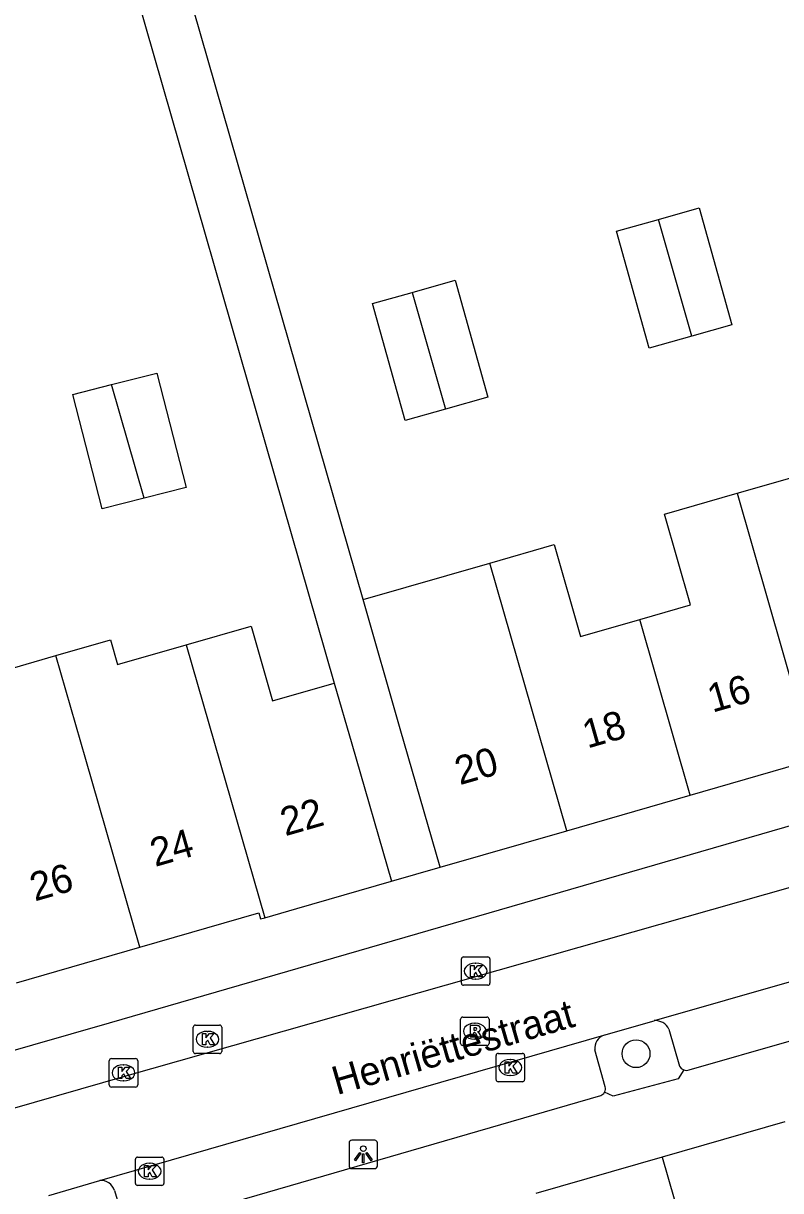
# Model space of a CAD drawing. Extents: x 159718 to 160783, y 383290 to 384030.
# Drawn here: x 160324.72 to 160351.34, y 383596.25 to 383637.31 of the extents above; entities that cross this region are included whole.
import ezdxf

# ---------------------------------------------------------------- set-up
doc = ezdxf.new("R2010")
doc.units = 0
for name, color, linetype in [('IMGEO_Boom', 7, 'Continuous'), ('IMGEO_Kolk', 7, 'Continuous'), ('IMGEO_Lichtpunt', 7, 'Continuous'), ('IMGEO_Openbare_ruimte_label', 7, 'Continuous'), ('IMGEO_Pand', 7, 'Continuous'), ('IMGEO_Pand_nummerreeks', 7, 'Continuous'), ('IMGEO_Parkeervlak_open', 7, 'Continuous'), ('IMGEO_Rijbaan_lokaal_open', 7, 'Continuous'), ('IMGEO_Rioolput', 7, 'Continuous'), ('IMGEO_Voetpad_open', 7, 'Continuous')]:
    doc.layers.add(name, color=color, linetype=linetype)

msp = doc.modelspace()

# ---------------------------------------------------------------- linework, layer by layer
at = {"layer": 'IMGEO_Boom'}
msp.add_circle((160346.26, 383601.066), 0.489, dxfattribs=at)
at = {"layer": 'IMGEO_Kolk'}
for p, q in [((160340.118, 383603.547), (160340.118, 383604.399)), ((160340.193, 383604.473), (160341.045, 383604.473)), ((160341.119, 383604.399), (160341.119, 383603.547)), ((160340.606, 383604.253), (160340.631, 383604.253)), ((160340.629, 383603.693), (160340.604, 383603.693)), ((160341.045, 383603.473), (160340.193, 383603.473)), ((160330.69, 383601.148), (160330.69, 383602)), ((160330.765, 383602.074), (160331.617, 383602.074)), ((160331.178, 383601.854), (160331.203, 383601.854)), ((160331.691, 383602), (160331.691, 383601.148)), ((160331.617, 383601.074), (160330.765, 383601.074)), ((160331.201, 383601.294), (160331.176, 383601.294)), ((160341.414, 383601.08), (160342.266, 383601.08)), ((160327.737, 383599.967), (160327.737, 383600.819)), ((160327.812, 383600.893), (160328.664, 383600.893)), ((160328.225, 383600.673), (160328.25, 383600.673)), ((160328.738, 383600.819), (160328.738, 383599.967)), ((160341.339, 383600.154), (160341.339, 383601.006)), ((160341.827, 383600.86), (160341.852, 383600.86)), ((160342.34, 383601.006), (160342.34, 383600.154)), ((160341.85, 383600.3), (160341.825, 383600.3)), ((160328.664, 383599.893), (160327.812, 383599.893)), ((160328.248, 383600.113), (160328.223, 383600.113)), ((160342.266, 383600.08), (160341.414, 383600.08)), ((160328.659, 383596.506), (160328.659, 383597.358)), ((160328.734, 383597.432), (160329.586, 383597.432)), ((160329.66, 383597.358), (160329.66, 383596.506)), ((160329.147, 383597.212), (160329.172, 383597.212)), ((160329.17, 383596.652), (160329.145, 383596.652)), ((160329.586, 383596.432), (160328.734, 383596.432))]:
    msp.add_line(p, q, dxfattribs=at)
for points in [[(160340.118, 383603.547), (160340.118, 383604.399)], [(160340.193, 383604.473), (160341.045, 383604.473)], [(160341.119, 383604.399), (160341.119, 383603.547)], [(160340.439, 383604.173), (160340.562, 383604.173), (160340.562, 383604.022), (160340.692, 383604.173), (160340.856, 383604.173), (160340.71, 383604.022), (160340.863, 383603.773), (160340.711, 383603.773), (160340.626, 383603.937), (160340.562, 383603.87), (160340.562, 383603.773), (160340.439, 383603.773), (160340.439, 383604.173)], [(160341.045, 383603.473), (160340.193, 383603.473)], [(160330.69, 383601.148), (160330.69, 383602)], [(160330.765, 383602.074), (160331.617, 383602.074)], [(160331.691, 383602), (160331.691, 383601.148)], [(160331.011, 383601.774), (160331.134, 383601.774), (160331.134, 383601.623), (160331.264, 383601.774), (160331.428, 383601.774), (160331.282, 383601.623), (160331.435, 383601.374), (160331.283, 383601.374), (160331.198, 383601.538), (160331.134, 383601.471), (160331.134, 383601.374), (160331.011, 383601.374), (160331.011, 383601.774)], [(160331.617, 383601.074), (160330.765, 383601.074)], [(160341.414, 383601.08), (160342.266, 383601.08)], [(160327.737, 383599.967), (160327.737, 383600.819)], [(160327.812, 383600.893), (160328.664, 383600.893)], [(160328.738, 383600.819), (160328.738, 383599.967)], [(160341.339, 383600.154), (160341.339, 383601.006)], [(160341.66, 383600.78), (160341.783, 383600.78), (160341.783, 383600.629), (160341.913, 383600.78), (160342.077, 383600.78), (160341.931, 383600.629), (160342.084, 383600.38), (160341.932, 383600.38), (160341.847, 383600.544), (160341.783, 383600.477), (160341.783, 383600.38), (160341.66, 383600.38), (160341.66, 383600.78)], [(160342.34, 383601.006), (160342.34, 383600.154)], [(160328.058, 383600.593), (160328.181, 383600.593), (160328.181, 383600.442), (160328.311, 383600.593), (160328.475, 383600.593), (160328.329, 383600.442), (160328.482, 383600.193), (160328.33, 383600.193), (160328.245, 383600.357), (160328.181, 383600.29), (160328.181, 383600.193), (160328.058, 383600.193), (160328.058, 383600.593)], [(160328.664, 383599.893), (160327.812, 383599.893)], [(160342.266, 383600.08), (160341.414, 383600.08)], [(160328.659, 383596.506), (160328.659, 383597.358)], [(160328.734, 383597.432), (160329.586, 383597.432)], [(160329.66, 383597.358), (160329.66, 383596.506)], [(160328.98, 383597.132), (160329.103, 383597.132), (160329.103, 383596.981), (160329.233, 383597.132), (160329.397, 383597.132), (160329.251, 383596.981), (160329.404, 383596.732), (160329.252, 383596.732), (160329.167, 383596.896), (160329.103, 383596.829), (160329.103, 383596.732), (160328.98, 383596.732), (160328.98, 383597.132)], [(160329.586, 383596.432), (160328.734, 383596.432)]]:
    msp.add_lwpolyline(points, dxfattribs=at)
for centre, start, end in [((160340.195, 383604.397), 91.552, 178.448), ((160340.195, 383604.397), 91.552, 178.448), ((160341.043, 383604.397), 1.552, 88.448), ((160341.043, 383604.397), 1.552, 88.448), ((160340.195, 383603.549), 181.552, 268.448), ((160340.195, 383603.549), 181.552, 268.448), ((160341.043, 383603.549), 271.552, 358.448), ((160341.043, 383603.549), 271.552, 358.448), ((160330.767, 383601.998), 91.552, 178.448), ((160330.767, 383601.998), 91.552, 178.448), ((160331.615, 383601.998), 1.552, 88.448), ((160331.615, 383601.998), 1.552, 88.448), ((160330.767, 383601.15), 181.552, 268.448), ((160330.767, 383601.15), 181.552, 268.448), ((160331.615, 383601.15), 271.552, 358.448), ((160331.615, 383601.15), 271.552, 358.448), ((160341.416, 383601.004), 91.552, 178.448), ((160341.416, 383601.004), 91.552, 178.448), ((160342.264, 383601.004), 1.552, 88.448), ((160342.264, 383601.004), 1.552, 88.448), ((160327.814, 383600.817), 91.552, 178.448), ((160327.814, 383600.817), 91.552, 178.448), ((160328.662, 383600.817), 1.552, 88.448), ((160328.662, 383600.817), 1.552, 88.448), ((160327.814, 383599.969), 181.552, 268.448), ((160327.814, 383599.969), 181.552, 268.448), ((160328.662, 383599.969), 271.552, 358.448), ((160328.662, 383599.969), 271.552, 358.448), ((160341.416, 383600.156), 181.552, 268.448), ((160341.416, 383600.156), 181.552, 268.448), ((160342.264, 383600.156), 271.552, 358.448), ((160342.264, 383600.156), 271.552, 358.448), ((160328.736, 383597.356), 91.552, 178.448), ((160328.736, 383597.356), 91.552, 178.448), ((160329.584, 383597.356), 1.552, 88.448), ((160329.584, 383597.356), 1.552, 88.448), ((160328.736, 383596.508), 181.552, 268.448), ((160328.736, 383596.508), 181.552, 268.448), ((160329.584, 383596.508), 271.552, 358.448), ((160329.584, 383596.508), 271.552, 358.448)]:
    msp.add_arc(centre, 0.0765, start, end, dxfattribs=at)
for centre, major_axis, ratio, start_param, end_param in [((160340.605, 383603.973), (-0.387, 0.002), 0.722429, 4.712389, 7.853982), ((160340.63, 383603.973), (-0.39, 0.002), 0.717154, 1.570796, 4.712389), ((160331.177, 383601.574), (-0.387, 0.002), 0.722429, 4.712389, 7.853982), ((160331.202, 383601.574), (-0.39, 0.002), 0.717154, 1.570796, 4.712389), ((160328.224, 383600.393), (-0.387, 0.002), 0.722429, 4.712389, 7.853982), ((160328.249, 383600.393), (-0.39, 0.002), 0.717154, 1.570796, 4.712389), ((160341.826, 383600.58), (-0.387, 0.002), 0.722429, 4.712389, 7.853982), ((160341.851, 383600.58), (-0.39, 0.002), 0.717154, 1.570796, 4.712389), ((160329.146, 383596.932), (-0.387, 0.002), 0.722429, 4.712389, 7.853982), ((160329.171, 383596.932), (-0.39, 0.002), 0.717154, 1.570796, 4.712389)]:
    msp.add_ellipse(centre, major_axis=major_axis, ratio=ratio, start_param=start_param, end_param=end_param, dxfattribs=at)
at = {"layer": 'IMGEO_Lichtpunt'}
for p, q in [((160336.17, 383597.929), (160336.17, 383597.122)), ((160336.17, 383597.929), (160336.17, 383597.122)), ((160337.072, 383598.024), (160336.264, 383598.024)), ((160337.072, 383598.024), (160336.264, 383598.024)), ((160337.166, 383597.122), (160337.166, 383597.929)), ((160337.166, 383597.122), (160337.166, 383597.929)), ((160336.264, 383597.028), (160337.072, 383597.028)), ((160336.264, 383597.028), (160337.072, 383597.028))]:
    msp.add_line(p, q, dxfattribs=at)
for points in [[(160336.544, 383597.593), (160336.583, 383597.565), (160336.395, 383597.303), (160336.357, 383597.33), (160336.544, 383597.593)], [(160336.646, 383597.545), (160336.693, 383597.545), (160336.693, 383597.223), (160336.646, 383597.223), (160336.646, 383597.545)], [(160336.756, 383597.565), (160336.794, 383597.592), (160336.981, 383597.33), (160336.942, 383597.302), (160336.756, 383597.565)]]:
    msp.add_lwpolyline(points, dxfattribs=at)
msp.add_circle((160336.669, 383597.727), 0.0994, dxfattribs=at)
for centre, start, end in [((160336.264, 383597.929), 90, 180), ((160336.264, 383597.929), 90, 180), ((160337.072, 383597.929), 0, 90), ((160337.072, 383597.929), 0, 90), ((160336.264, 383597.122), 180, 270), ((160336.264, 383597.122), 180, 270), ((160337.072, 383597.122), 270, 0), ((160337.072, 383597.122), 270, 360)]:
    msp.add_arc(centre, 0.0946, start, end, dxfattribs=at)
at = {"layer": 'IMGEO_Pand'}
for points in [[(160347.043, 383630.414), (160348.481, 383630.816), (160349.63, 383626.703), (160348.222, 383626.31)], [(160348.222, 383626.31), (160346.715, 383625.889), (160345.567, 383630.002), (160347.043, 383630.414)], [(160348.222, 383626.31), (160347.043, 383630.414)], [(160338.382, 383627.846), (160339.904, 383628.271), (160341.053, 383624.158), (160339.561, 383623.742)], [(160339.561, 383623.742), (160338.138, 383623.344), (160336.99, 383627.457), (160338.382, 383627.846)], [(160338.382, 383627.846), (160339.561, 383623.742)], [(160327.817, 383624.603), (160329.411, 383625.011), (160330.441, 383620.989), (160328.963, 383620.61)], [(160328.963, 383620.61), (160327.485, 383620.232), (160326.455, 383624.254), (160327.817, 383624.603)], [(160328.963, 383620.61), (160327.817, 383624.603)], [(160349.809, 383620.783), (160352.074, 383621.433), (160353.022, 383618.13), (160355.215, 383618.759)], [(160346.387, 383616.339), (160348.178, 383616.853), (160347.26, 383620.051), (160349.809, 383620.783)], [(160349.809, 383620.783), (160352.5, 383611.416)], [(160341.118, 383618.323), (160343.384, 383618.973), (160344.311, 383615.743), (160346.387, 383616.339)], [(160336.661, 383617.043), (160341.118, 383618.323)], [(160343.822, 383608.91), (160341.118, 383618.323)], [(160339.374, 383607.626), (160337.968, 383612.489), (160336.661, 383617.043)], [(160348.161, 383610.163), (160346.387, 383616.339)], [(160330.445, 383615.449), (160332.724, 383616.103), (160333.477, 383613.482), (160335.648, 383614.105)], [(160325.861, 383615.071), (160327.779, 383615.621), (160328.028, 383614.755), (160330.445, 383615.449)], [(160330.445, 383615.449), (160333.202, 383605.848)], [(160321.791, 383612.909), (160323.822, 383613.492), (160323.558, 383614.41), (160325.861, 383615.071)], [(160328.807, 383604.81), (160326.911, 383611.415), (160325.861, 383615.071)], [(160335.648, 383614.105), (160336.263, 383611.964), (160337.665, 383607.14)], [(160348.161, 383610.163), (160352.5, 383611.416)], [(160343.822, 383608.91), (160348.161, 383610.163)], [(160339.374, 383607.626), (160343.822, 383608.91)], [(160333.202, 383605.848), (160334.337, 383606.176), (160337.665, 383607.14)], [(160328.807, 383604.81), (160332.998, 383606.018), (160333.059, 383605.806), (160333.202, 383605.848)], [(160324.474, 383603.561), (160328.807, 383604.81)], [(160351.488, 383598.672), (160347.175, 383597.427)], [(160347.175, 383597.427), (160342.737, 383596.145)], [(160347.175, 383597.427), (160349.881, 383588.026)]]:
    msp.add_lwpolyline(points, dxfattribs=at)
at = {"layer": 'IMGEO_Parkeervlak_open'}
for points in [[(160360.615, 383611.67), (160327.739, 383602.146), (160280.384, 383588.556), (160278.661, 383588.057)], [(160347.413, 383601.928), (160347.791, 383600.63)], [(160345.177, 383599.907), (160344.812, 383601.202)], [(160327.919, 383596.25), (160328.296, 383594.994)]]:
    msp.add_lwpolyline(points, dxfattribs=at)
for centre, radius, start, end in [((160346.943, 383601.714), 0.517, 24.4842, 94.6141), ((160345.283, 383601.268), 0.475, 108.4756, 188.0131), ((160348.029, 383600.741), 0.263, 205.0743, 249.0459), ((160344.907, 383599.845), 0.276, 330.4513, 12.8836), ((160327.448, 383596.122), 0.488, 15.1794, 95.5224)]:
    msp.add_arc(centre, radius, start, end, dxfattribs=at)
at = {"layer": 'IMGEO_Rijbaan_lokaal_open'}
for points in [[(160319.597, 383597.777), (160328.281, 383600.276), (160360.238, 383609.357)], [(160361.709, 383606.473), (160346.901, 383602.229)], [(160345.132, 383601.719), (160346.901, 383602.229)], [(160327.401, 383596.608), (160345.132, 383601.719)], [(160325.619, 383596.076), (160327.401, 383596.608)]]:
    msp.add_lwpolyline(points, dxfattribs=at)
at = {"layer": 'IMGEO_Rioolput'}
for p, q in [((160340.09, 383601.43), (160340.09, 383602.282)), ((160340.165, 383602.356), (160341.017, 383602.356)), ((160341.091, 383602.282), (160341.091, 383601.43)), ((160340.578, 383602.136), (160340.603, 383602.136)), ((160340.601, 383601.576), (160340.576, 383601.576)), ((160341.017, 383601.356), (160340.165, 383601.356))]:
    msp.add_line(p, q, dxfattribs=at)
for points in [[(160340.09, 383601.43), (160340.09, 383602.282)], [(160340.165, 383602.356), (160341.017, 383602.356)], [(160341.091, 383602.282), (160341.091, 383601.43)], [(160340.679, 383602.054), (160340.427, 383602.056), (160340.427, 383601.656)], [(160340.605, 383601.975), (160340.551, 383601.975), (160340.551, 383601.894)], [(160340.551, 383601.894), (160340.603, 383601.894)], [(160340.427, 383601.656), (160340.551, 383601.656), (160340.551, 383601.818), (160340.562, 383601.818)], [(160340.609, 383601.789), (160340.68, 383601.656), (160340.82, 383601.656), (160340.755, 383601.782)], [(160341.017, 383601.356), (160340.165, 383601.356)]]:
    msp.add_lwpolyline(points, dxfattribs=at)
for centre, radius, start, end in [((160340.167, 383602.28), 0.0765, 91.552, 178.448), ((160340.167, 383602.28), 0.0765, 91.552, 178.448), ((160341.015, 383602.28), 0.0765, 1.552, 88.448), ((160341.015, 383602.28), 0.0765, 1.552, 88.448), ((160340.587, 383602.083), 0.19, 274.7715, 282.9687), ((160340.611, 383601.879), 0.0964, 77.0061, 93.1865), ((160340.625, 383601.936), 0.0378, 276.6634, 79.6772), ((160340.678, 383601.944), 0.109, 350.3612, 89.416), ((160340.676, 383601.944), 0.112, 277.5842, 350.9817), ((160340.66, 383601.729), 0.108, 29.5134, 73.7905), ((160340.167, 383601.432), 0.0765, 181.552, 268.448), ((160340.167, 383601.432), 0.0765, 181.552, 268.448), ((160340.561, 383601.765), 0.0533, 26.0293, 88.6989), ((160341.015, 383601.432), 0.0765, 271.552, 358.448), ((160341.015, 383601.432), 0.0765, 271.552, 358.448)]:
    msp.add_arc(centre, radius, start, end, dxfattribs=at)
for centre, major_axis, ratio, start_param, end_param in [((160340.577, 383601.856), (-0.387, 0.002), 0.722429, 4.712389, 7.853982), ((160340.602, 383601.856), (-0.39, 0.002), 0.717154, 1.570796, 4.712389)]:
    msp.add_ellipse(centre, major_axis=major_axis, ratio=ratio, start_param=start_param, end_param=end_param, dxfattribs=at)
at = {"layer": 'IMGEO_Voetpad_open'}
for points in [[(160336.661, 383617.043), (160328.617, 383645.07), (160351.197, 383651.165)], [(160309.377, 383606.68), (160300.547, 383637.418), (160326.889, 383644.599), (160335.648, 383614.105)], [(160337.665, 383607.14), (160339.374, 383607.626)], [(160348.125, 383600.497), (160362.518, 383604.626), (160364.459, 383605.305)], [(160347.935, 383600.496), (160347.739, 383600.182), (160345.456, 383599.57), (160345.148, 383599.709)], [(160328.613, 383594.837), (160345.017, 383599.594)]]:
    msp.add_lwpolyline(points, dxfattribs=at)
for centre, radius, start, end in [((160348.029, 383600.746), 0.267, 249.4272, 291.176), ((160344.91, 383599.848), 0.275, 292.8251, 329.7322)]:
    msp.add_arc(centre, radius, start, end, dxfattribs=at)

# ---------------------------------------------------------------- texts
at = {"layer": 'IMGEO_Openbare_ruimte_label'}
msp.add_text('Henriëttestraat', height=1, rotation=16.0792, dxfattribs=at).set_placement((160335.742, 383599.608))
at = {"layer": 'IMGEO_Pand_nummerreeks'}
for s, rotation, p in [('16', 16.0142, (160348.944, 383613.059)), ('18', 16.0142, (160344.548, 383611.798)), ('20', 16.0142, (160340.061, 383610.51)), ('22', 16.0084, (160333.924, 383608.713)), ('24', 16.0142, (160329.348, 383607.633)), ('26', 16.0142, (160325.12, 383606.419))]:
    msp.add_text(s, height=1, rotation=rotation, dxfattribs=at).set_placement(p)

doc.saveas('drawing.dxf')
